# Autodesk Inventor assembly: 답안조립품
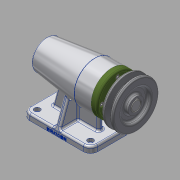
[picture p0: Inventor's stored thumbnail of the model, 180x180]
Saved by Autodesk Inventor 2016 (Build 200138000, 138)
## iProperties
Created: 2018-09
Part Number: 답안조립품
Document SubType Name: Assembly
Designer: Administrator
Author: Administrator
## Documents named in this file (12)
- C:\Users\Administrator\Desktop\480907V1001\답안조립품.iam
- C:\Users\Administrator\Desktop\480907V1001\본체.ipt
- C:\Users\Administrator\Desktop\480907V1001\베어링 51202.ipt
- C:\Users\Administrator\Desktop\480907V1001\어댑터슬리브.ipt
- C:\Users\Administrator\Desktop\480907V1001\볼트 M4.ipt
- C:\Users\Administrator\Desktop\480907V1001\축.ipt
- C:\Users\Administrator\Desktop\480907V1001\베어링 6004.ipt
- C:\Users\Administrator\Desktop\480907V1001\커버.ipt
- C:\Users\Administrator\Desktop\480907V1001\오일 실.ipt
- C:\Users\Administrator\Desktop\480907V1001\키 5 x 5 x 16.ipt
- C:\Users\Administrator\Desktop\480907V1001\V벨트풀리.ipt
- C:\Users\Administrator\Desktop\480907V1001\멈춤나사 M3.ipt
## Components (1 placed, 1 different names)
1. V벨트풀리:1
